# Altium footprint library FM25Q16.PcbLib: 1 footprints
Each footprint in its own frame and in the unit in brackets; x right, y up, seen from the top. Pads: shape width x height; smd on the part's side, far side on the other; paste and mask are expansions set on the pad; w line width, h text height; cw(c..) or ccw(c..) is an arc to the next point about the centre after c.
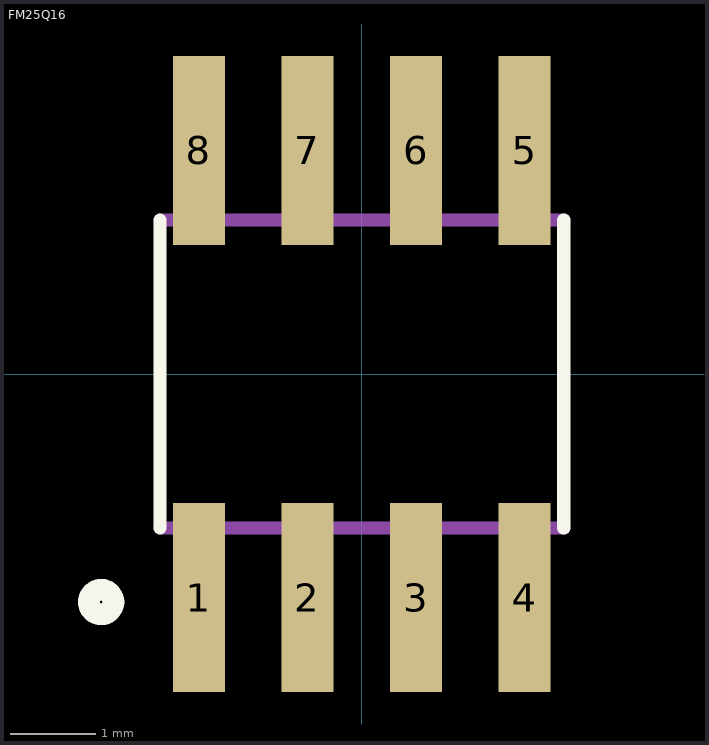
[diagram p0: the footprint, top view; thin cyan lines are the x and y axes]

## FM25Q16 [mil]
pads (8):
  rect 24x87 smd: 1(-75,-103) 2(-25,-103) 3(25,-103) 4(75,-103) 5(75,103) 6(25,103) 7(-25,103) 8(-75,103)
Top Overlay:
  circle w10: c-120,-105 r5.65
  lines w6: -92.99,-70.98 -92.99,70.98 ; 92.99,-70.98 92.99,70.98
Mechanical 13:
  region: -68,-113 -82,-113 -82,-73 -68,-73
  region: -18,-113 -32,-113 -32,-73 -18,-73
  region: 32,-113 18,-113 18,-73 32,-73
  region: 82,-113 68,-113 68,-73 82,-73
  region: -68,73 -82,73 -82,113 -68,113
  region: -18,73 -32,73 -32,113 -18,113
  region: 32,73 18,73 18,113 32,113
  region: 82,73 68,73 68,113 82,113
  lines w6: -92.99,-70.98 92.99,-70.98 ; -92.99,70.98 92.99,70.98
3D body "FM25Q16.STEP": height 68.9, standoff 0, extent -96.46,-118.1 96.45,118.11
